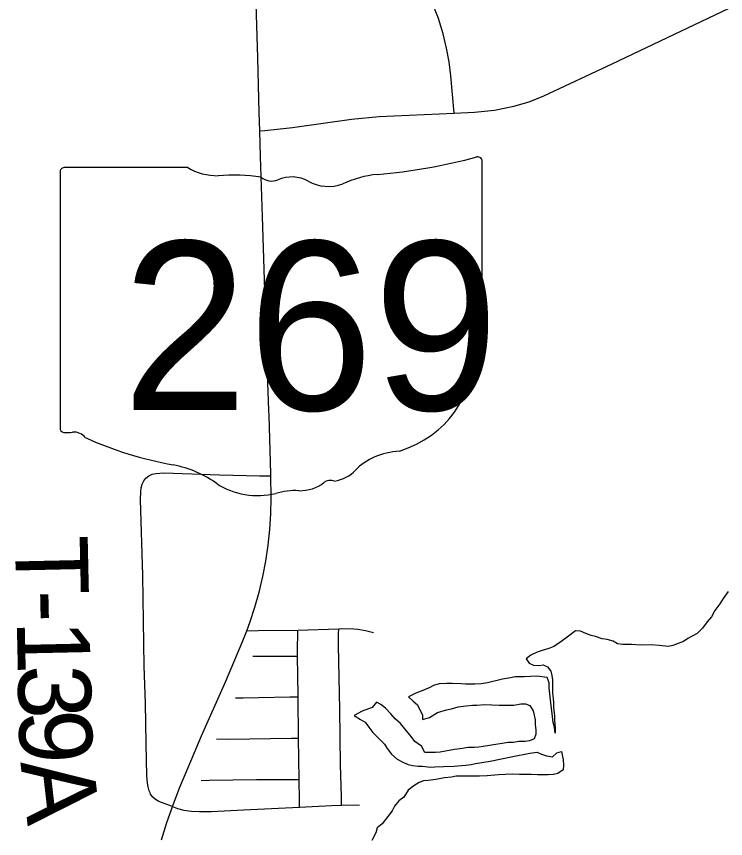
# Model space of a CAD drawing. Extents: x 63.4 to 97.4, y 0.4 to 22.4.
# Drawn here: x 69.385 to 69.939, y 18.029 to 18.671 of the extents above; entities that cross this region are included whole.
import ezdxf

# ---------------------------------------------------------------- set-up
doc = ezdxf.new("R2010")
doc.units = 0
for name, color, linetype in [('GM_X_Minor_River', 7, 'Continuous'), ('GM_X_State_Location', 7, 'Continuous'), ('GM_X_State_Route', 7, 'Continuous'), ('GM_X_State_Shield', 7, 'Continuous'), ('GM_X_Township_Road', 7, 'Continuous'), ('GM_X_Township_Road_Text', 7, 'Continuous')]:
    doc.layers.add(name, color=color, linetype=linetype)

msp = doc.modelspace()

# ---------------------------------------------------------------- linework, layer by layer
at = {"layer": 'GM_X_Minor_River'}
for points in [[(69.94113, 18.22206), (69.93736, 18.21672), (69.93473, 18.21253), (69.93096, 18.20719), (69.92833, 18.20223), (69.92493, 18.19841), (69.92116, 18.19346)], [(69.94113, 18.22206), (69.93736, 18.21672), (69.93473, 18.21253), (69.93096, 18.20719), (69.92833, 18.20223), (69.92493, 18.19841), (69.92116, 18.19346)], [(69.92116, 18.19346), (69.917, 18.18925), (69.90981, 18.18542), (69.90641, 18.18312), (69.89807, 18.18004), (69.89465, 18.17926), (69.88744, 18.17999), (69.88136, 18.18034), (69.87339, 18.18031), (69.86579, 18.18065), (69.85896, 18.18062), (69.85478, 18.18136), (69.85135, 18.18324), (69.84679, 18.18474), (69.84299, 18.1851), (69.83767, 18.18698), (69.83425, 18.18773), (69.83006, 18.18923), (69.82588, 18.19111), (69.82208, 18.19147), (69.81565, 18.1865), (69.80884, 18.18152), (69.80506, 18.17922), (69.80127, 18.17769), (69.79596, 18.17614), (69.79217, 18.1746), (69.78725, 18.1723), (69.78346, 18.16962), (69.78576, 18.16621), (69.78918, 18.1647), (69.79336, 18.16434), (69.79678, 18.16474), (69.8002, 18.16323), (69.80288, 18.15983), (69.80365, 18.15641), (69.80405, 18.15299), (69.8041, 18.14273), (69.8045, 18.13855), (69.8049, 18.13512), (69.80492, 18.13132), (69.80571, 18.12525), (69.80573, 18.12144), (69.80614, 18.11536), (69.80616, 18.11156), (69.80576, 18.11612), (69.8046, 18.11992), (69.8038, 18.12676), (69.80302, 18.13284), (69.80142, 18.14689), (69.8014, 18.15069), (69.79986, 18.15487), (69.79189, 18.15597), (69.78202, 18.15555), (69.7748, 18.15551), (69.77139, 18.15474), (69.76494, 18.15357), (69.75319, 18.15085), (69.74826, 18.15006), (69.74332, 18.14966), (69.73611, 18.14963), (69.73269, 18.14999), (69.72585, 18.15034), (69.72168, 18.15032), (69.71561, 18.14991), (69.71106, 18.14875), (69.70765, 18.14683), (69.70159, 18.14414), (69.69742, 18.1426), (69.69174, 18.13991), (69.69517, 18.13651), (69.6986, 18.13348), (69.70244, 18.12552), (69.70246, 18.1221), (69.70815, 18.12365), (69.7142, 18.12748), (69.7214, 18.12979), (69.7252, 18.13057), (69.7305, 18.13211), (69.73657, 18.1329), (69.74151, 18.13331), (69.74492, 18.13332), (69.751, 18.13373), (69.76239, 18.13341), (69.77378, 18.13346), (69.77947, 18.13425), (69.78288, 18.13426), (69.78631, 18.13314), (69.78898, 18.12897), (69.78976, 18.12555), (69.79054, 18.12175), (69.79056, 18.11795), (69.79096, 18.11415), (69.79098, 18.11073), (69.78986, 18.10692), (69.78607, 18.10538), (69.78266, 18.10499), (69.77772, 18.10497), (69.77355, 18.10419), (69.76937, 18.10416), (69.76482, 18.10338), (69.7614, 18.10299)], [(69.7614, 18.10299), (69.75002, 18.10103), (69.74661, 18.10064), (69.7432, 18.10024), (69.73788, 18.10022), (69.73371, 18.09944), (69.72764, 18.09865), (69.71626, 18.09669), (69.71284, 18.0963), (69.70449, 18.09626), (69.70181, 18.10119), (69.69647, 18.10496), (69.6938, 18.10875), (69.68998, 18.1133), (69.68539, 18.11898), (69.6812, 18.12276), (69.67776, 18.12654), (69.67356, 18.13109), (69.67013, 18.13373), (69.6667, 18.13561), (69.66331, 18.13142), (69.65535, 18.12872), (69.64929, 18.12527), (69.65424, 18.12225), (69.65767, 18.11998), (69.66073, 18.1162), (69.66379, 18.11203), (69.67295, 18.10295), (69.67486, 18.09954), (69.6783, 18.09499), (69.68288, 18.09121), (69.68783, 18.08858), (69.69125, 18.08707), (69.69467, 18.08633), (69.69923, 18.08559), (69.70265, 18.0856), (69.70873, 18.08487), (69.71214, 18.08527), (69.71897, 18.0853), (69.72732, 18.08572), (69.73302, 18.08613), (69.73643, 18.08652), (69.74061, 18.08692), (69.74402, 18.0877), (69.7554, 18.08966), (69.77322, 18.09316), (69.7865, 18.09588), (69.79219, 18.09667), (69.79561, 18.09517), (69.79942, 18.09366), (69.80398, 18.09293), (69.80738, 18.09598), (69.81117, 18.09714), (69.81234, 18.09068), (69.81274, 18.0865), (69.81238, 18.0827), (69.80822, 18.08002), (69.80481, 18.07924), (69.80063, 18.07884), (69.79228, 18.0788), (69.78734, 18.07916), (69.77823, 18.07912), (69.77253, 18.07947), (69.76722, 18.07907), (69.76191, 18.07904), (69.75318, 18.07824), (69.74711, 18.07783), (69.72888, 18.07775), (69.72509, 18.07697), (69.71978, 18.07656), (69.71295, 18.07539), (69.70688, 18.0746), (69.70346, 18.0742), (69.70005, 18.07305), (69.69589, 18.07037), (69.69135, 18.06692), (69.68796, 18.06159), (69.68418, 18.05853), (69.68079, 18.05433), (69.67891, 18.0509), (69.67551, 18.04632), (69.67098, 18.0406), (69.6672, 18.03754), (69.66609, 18.03373), (69.66308, 18.02764)]]:
    msp.add_lwpolyline(points, dxfattribs=at)
at = {"layer": 'GM_X_State_Route'}
for points in [[(69.58254, 18.36366), (69.58148, 18.39235), (69.57927, 18.46566), (69.57766, 18.51493), (69.57605, 18.562), (69.57547, 18.5819), (69.57504, 18.59625), (69.57384, 18.63911), (69.57102, 18.73185), (69.5701, 18.76869), (69.56979, 18.77749)], [(69.49881, 18.02802), (69.50301, 18.04164), (69.50647, 18.05181), (69.50735, 18.05415), (69.51307, 18.0693), (69.52022, 18.08652), (69.53009, 18.10931), (69.54897, 18.15198), (69.56228, 18.18349), (69.56533, 18.19146), (69.56782, 18.19798), (69.57168, 18.20976), (69.57504, 18.22169), (69.57792, 18.23376), (69.58027, 18.24593), (69.58213, 18.25819), (69.58343, 18.27051), (69.58415, 18.28287), (69.58434, 18.29528), (69.58418, 18.31237), (69.58417, 18.31393), (69.58269, 18.35971), (69.58254, 18.36366)]]:
    msp.add_lwpolyline(points, dxfattribs=at)
at = {"layer": 'GM_X_State_Shield'}
for p, q in [((69.51931, 18.55328), (69.42279, 18.55328)), ((69.74912, 18.45356), (69.74912, 18.55824)), ((69.41954, 18.54984), (69.41954, 18.34972)), ((69.74909, 18.45358), (69.74912, 18.45356))]:
    msp.add_line(p, q, dxfattribs=at)
for centre, major_axis, start_param, end_param in [((69.63172, 18.82612), (0.34952, 0), 4.814394, 5.042369), ((69.74547, 18.55868), (0.00367, 0), 6.141152, 7.989035), ((69.42332, 18.55027), (0.00382, 0), 1.712693, 3.28349), ((69.54229, 18.57652), (0.03703, 0), 4.042523, 4.731795), ((69.55457, 18.44094), (0.13295, 0), 1.404758, 1.657858), ((69.60044, 18.52818), (0.02221, 0), 0.950623, 2.079405), ((69.6763, 18.49216), (0.07032, 0), 1.699011, 2.107814), ((69.58475, 18.55131), (0.01068, 0), 3.836095, 5.185415), ((69.62911, 18.5599), (0.02672, 0), 4.081561, 5.145723), ((69.74828, 18.44587), (0.00568, 0), 1.883978, 3.671073), ((69.74521, 18.45315), (0.00393, 0), 5.05454, 6.418171), ((69.71215, 18.43264), (0.03409, 0), 5.934695, 6.695948), ((69.76227, 18.40975), (0.0248, 0), 2.387724, 3.262537), ((69.6513, 18.39643), (0.08742, 0), 5.101752, 6.440018), ((69.42335, 18.34928), (0.00385, 0), 3.00124, 4.508301), ((69.42393, 18.36976), (0.0294, 0), 4.665946, 4.897461), ((69.42995, 18.33818), (0.0106, 0), 0.519207, 1.627899), ((69.56377, 18.51798), (0.2524, 0), 4.195997, 4.488961), ((69.68816, 18.29354), (0.04788, 0), 1.647645, 2.488434), ((69.48852, 18.25982), (0.07897, 0), 0.823519, 1.323587), ((69.6275, 18.33033), (0.02824, 0), 4.937069, 5.64225), ((69.63071, 18.30281), (0.00752, 0), 1.147584, 2.315152), ((69.57394, 18.33718), (0.05011, 0), 4.026481, 4.996735), ((69.60655, 18.3222), (0.0267, 0), 4.691044, 5.507374), ((69.60289, 18.26799), (0.04118, 0), 1.495662, 1.94098)]:
    msp.add_ellipse(centre, major_axis=major_axis, ratio=0.8, start_param=start_param, end_param=end_param, dxfattribs=at)
at = {"layer": 'GM_X_Township_Road'}
for p, q in [((69.60519, 18.19202), (69.63718, 18.19304)), ((69.60583, 18.10763), (69.60542, 18.13993)), ((69.60622, 18.07517), (69.60583, 18.10763)), ((69.63927, 18.05514), (69.65328, 18.05558))]:
    msp.add_line(p, q, dxfattribs=at)
for points in [[(69.72737, 18.59575), (69.72479, 18.625), (69.7234, 18.63578), (69.72136, 18.64666), (69.71858, 18.65779), (69.71501, 18.6697), (69.70933, 18.68421), (69.69194, 18.72079), (69.689, 18.72965), (69.68818, 18.73329), (69.68774, 18.73601), (69.68731, 18.73896), (69.68708, 18.74169), (69.68719, 18.74693), (69.68741, 18.75282), (69.68774, 18.75816), (69.6885, 18.76643)], [(69.72737, 18.59575), (69.74326, 18.59646), (69.75868, 18.59822), (69.77392, 18.60118), (69.78582, 18.60468), (69.79731, 18.60937), (69.85074, 18.63427), (69.95792, 18.68559)], [(69.57547, 18.5819), (69.57945, 18.58232), (69.60104, 18.58461), (69.64717, 18.59113), (69.66881, 18.59307), (69.72737, 18.59575)], [(69.48978, 18.06478), (69.48898, 18.06653), (69.48827, 18.06941), (69.48788, 18.07243), (69.48739, 18.07809), (69.48678, 18.10333), (69.48637, 18.13477), (69.48517, 18.16381), (69.48404, 18.23459), (69.48243, 18.29388), (69.48251, 18.30006), (69.48289, 18.30309), (69.48364, 18.30593), (69.48484, 18.30851), (69.48655, 18.31073), (69.48878, 18.31248), (69.49144, 18.31368), (69.49436, 18.31435), (69.49735, 18.31466), (69.50045, 18.31472), (69.54409, 18.31337), (69.57529, 18.31259), (69.58418, 18.31237)], [(69.63927, 18.05514), (69.63923, 18.05881), (69.6392, 18.06192), (69.63852, 18.08674), (69.63791, 18.1302), (69.63689, 18.17985), (69.63709, 18.18916), (69.63718, 18.19304)], [(69.63718, 18.19304), (69.63962, 18.19312), (69.64894, 18.19295), (69.65204, 18.19266), (69.65816, 18.19155), (69.66423, 18.19012)], [(69.56533, 18.19146), (69.57424, 18.19158), (69.60519, 18.19202)], [(69.60502, 18.17164), (69.60494, 18.17858), (69.60512, 18.18801), (69.60519, 18.19202)], [(69.56997, 18.17148), (69.59824, 18.17161), (69.60502, 18.17164)], [(69.60542, 18.13993), (69.60541, 18.14082), (69.60502, 18.17164)], [(69.55651, 18.13911), (69.56259, 18.13903), (69.57474, 18.13924), (69.59903, 18.13979), (69.60542, 18.13993)], [(69.54174, 18.10701), (69.55098, 18.10671), (69.60026, 18.10754), (69.60583, 18.10763)], [(69.52978, 18.07451), (69.53593, 18.07466), (69.57284, 18.0752), (69.60053, 18.07518), (69.60622, 18.07517)], [(69.60649, 18.05366), (69.60642, 18.05903), (69.60622, 18.07517)], [(69.50735, 18.05415), (69.50381, 18.05546), (69.49659, 18.05813), (69.49403, 18.05965), (69.49185, 18.06158), (69.49018, 18.0639), (69.48978, 18.06478)], [(69.50735, 18.05415), (69.51129, 18.05255), (69.51607, 18.05137), (69.52226, 18.05051), (69.52849, 18.05016), (69.53785, 18.0503), (69.56281, 18.0515), (69.60649, 18.05366)], [(69.60649, 18.05366), (69.63143, 18.05489), (69.63927, 18.05514)]]:
    msp.add_lwpolyline(points, dxfattribs=at)

# ---------------------------------------------------------------- texts
at = {"layer": 'GM_X_State_Location'}
for s, p in [('r', (69.58062, 18.43648)), ('s', (69.58063, 18.43648))]:
    msp.add_text(s, height=0.000189, dxfattribs=at).set_placement(p)
msp.add_text('269', height=0.000189, rotation=0.00001, dxfattribs=at).set_placement((69.51377, 18.4227))
at = {"layer": 'GM_X_State_Shield'}
msp.add_text('269', height=0.131836, dxfattribs=at).set_placement((69.46801, 18.36383))
at = {"layer": 'GM_X_Township_Road_Text'}
for s, rotation, p in [('T', 271.26009, (69.38425, 18.26524)), ('-', 271.25916, (69.38518, 18.22275)), ('1', 271.26494, (69.3857, 18.19942)), ('3', 271.30595, (69.38648, 18.16438)), ('9', 271.44886, (69.38727, 18.12924)), ('A', 276.5164, (69.38854, 18.08877))]:
    msp.add_text(s, height=0.05682, rotation=rotation, dxfattribs=at).set_placement(p)

doc.saveas('drawing.dxf')
